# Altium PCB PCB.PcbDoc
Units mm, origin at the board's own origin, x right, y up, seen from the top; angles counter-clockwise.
Board outline 41 x 25.36 mm, 2 copper layers (TOP, BOTTOM), stack 1.586 mm thick; 68 components, 25 nets, 184 pads, 70 vias.
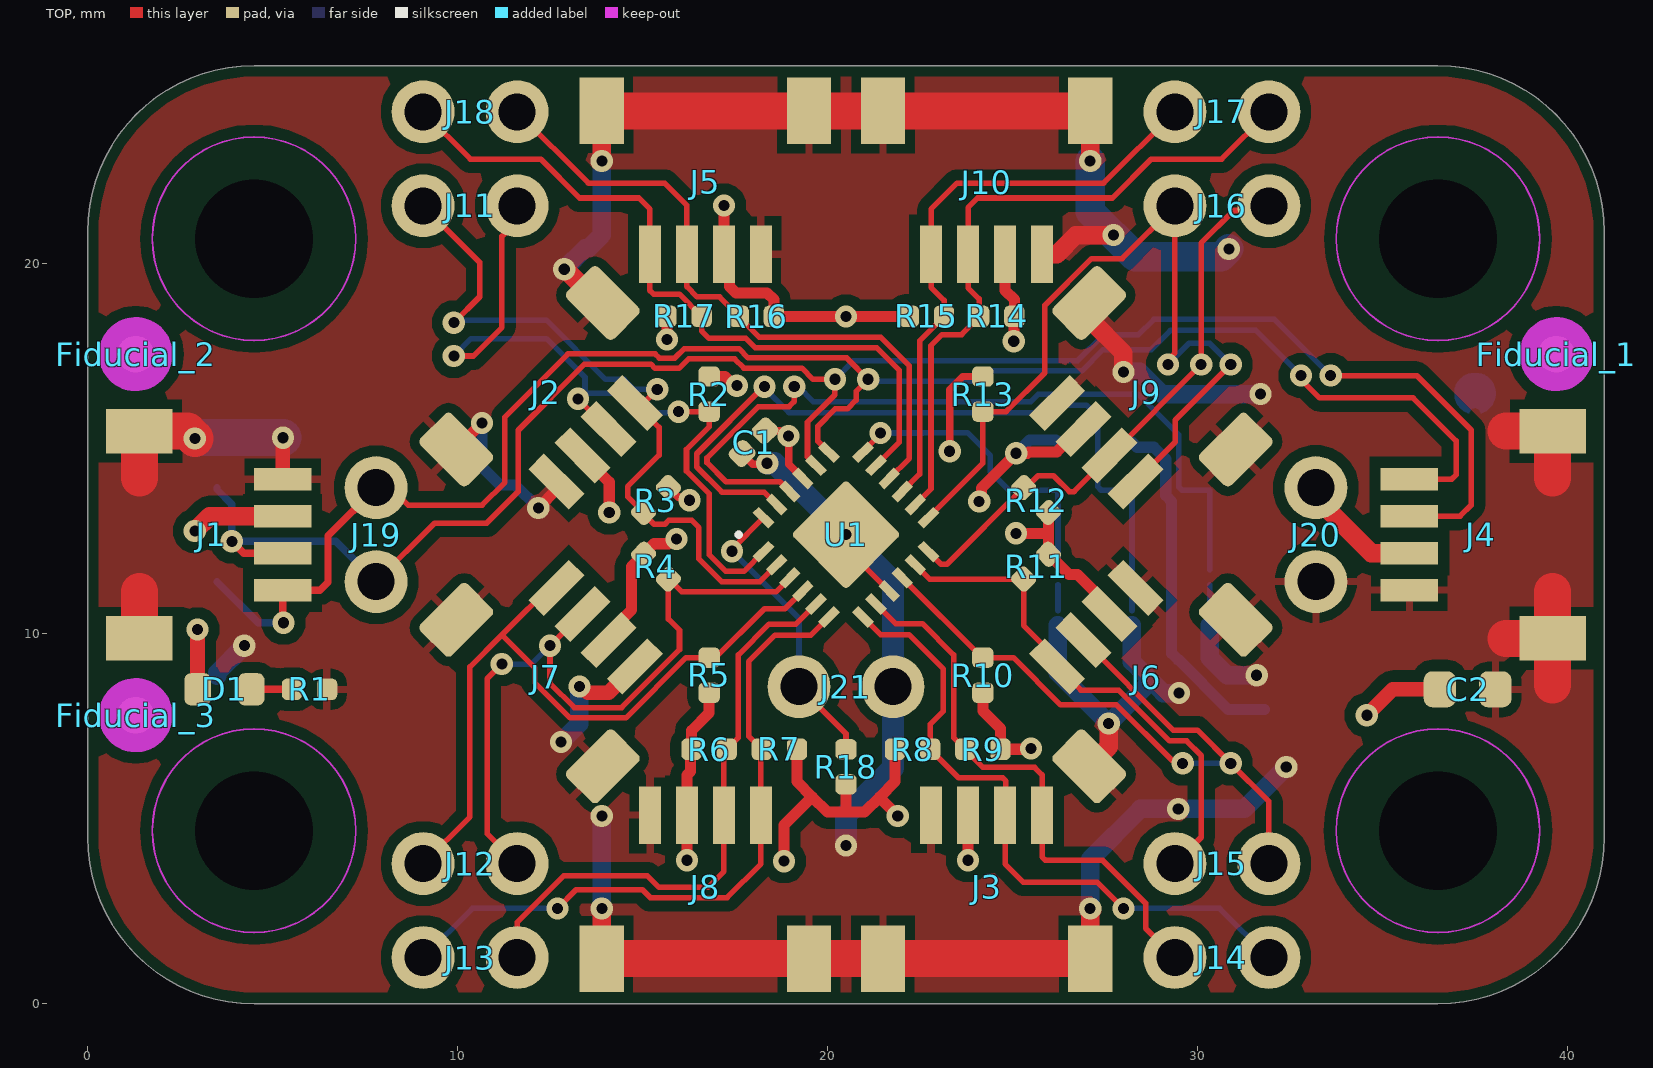
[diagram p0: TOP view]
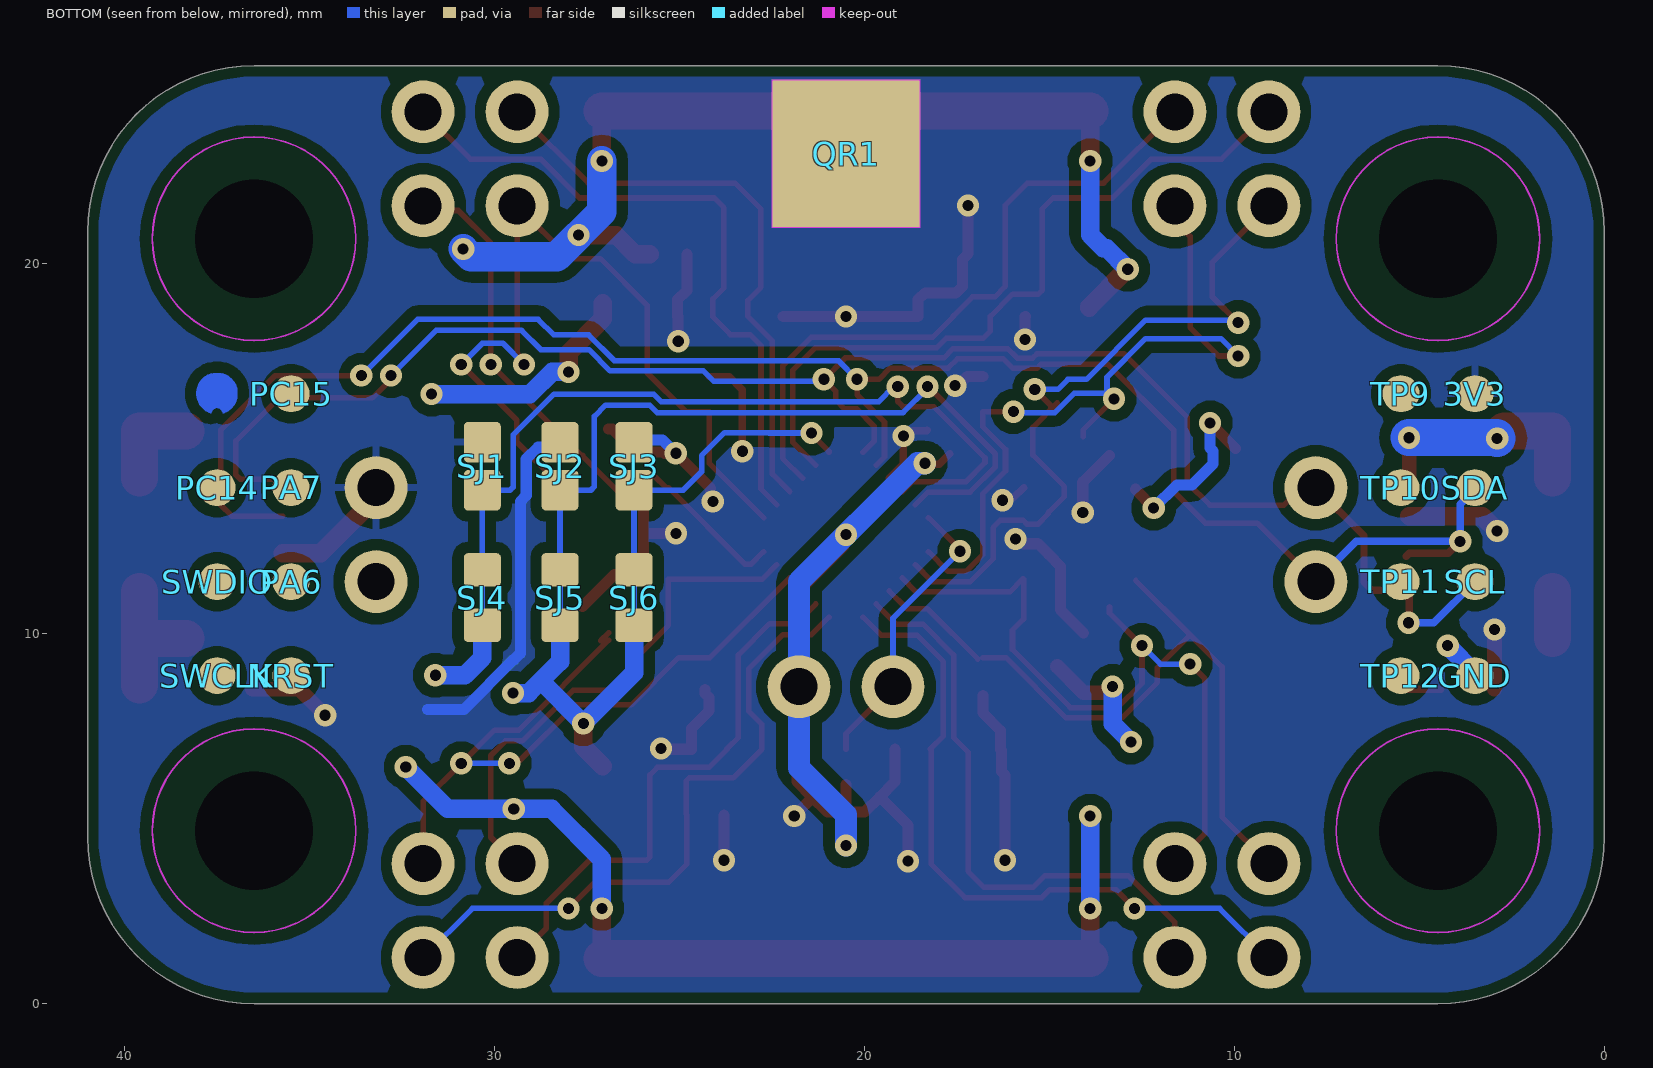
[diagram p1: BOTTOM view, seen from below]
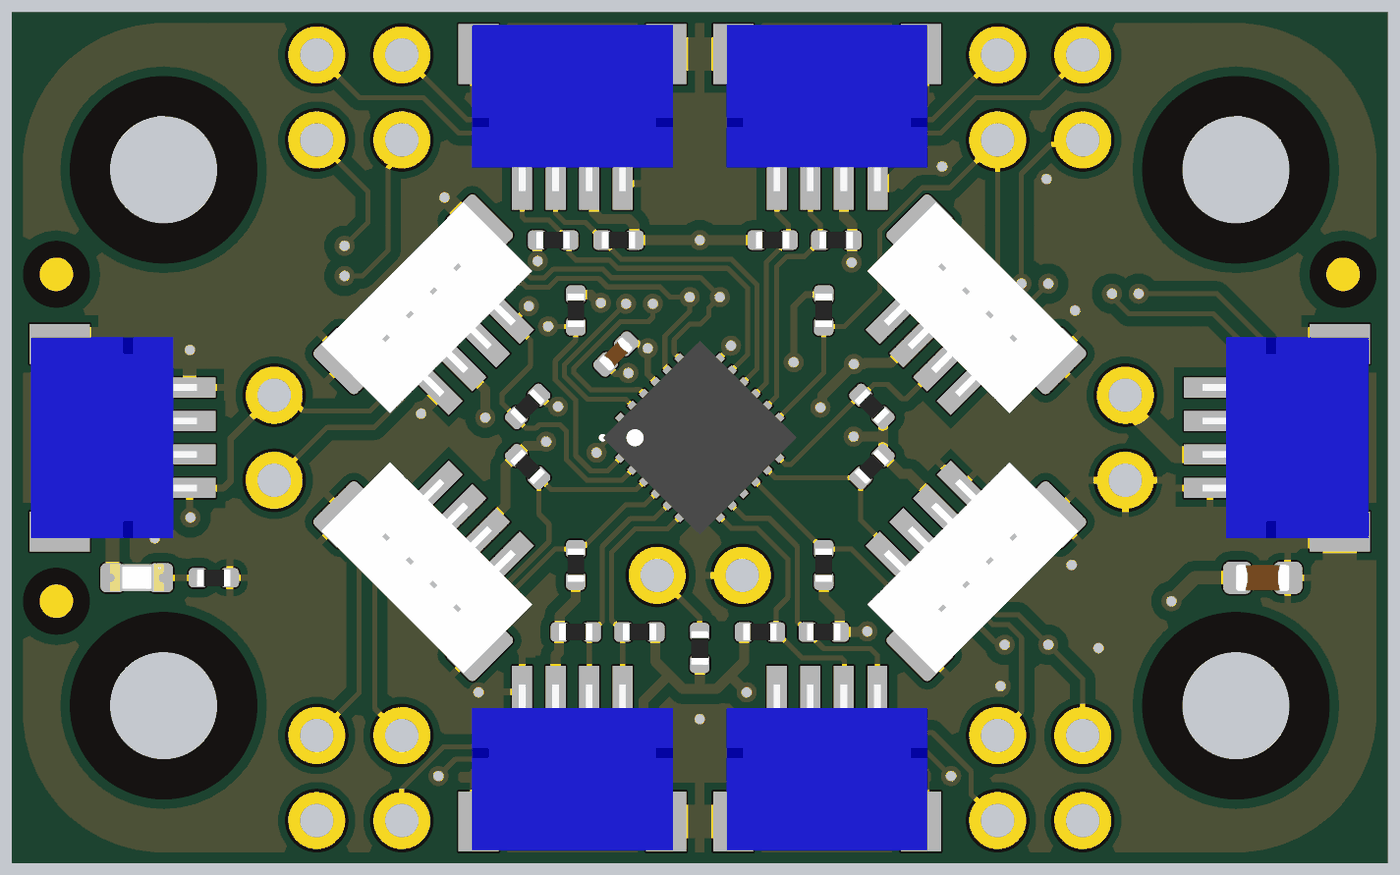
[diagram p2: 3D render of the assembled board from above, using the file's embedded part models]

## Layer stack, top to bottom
Top Solder: solder mask 0.01, Solder Resist, Dk 3.5
TOP: signal copper 0.018
Dielectric: core 1.55, FR-4, Dk 4.8
BOTTOM: signal copper 0.018
Bottom Solder: solder mask 0.01, Solder Resist, Dk 3.5

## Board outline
0,4.5 0,20.86 cw(c4.5,20.86) 4.5,25.36 36.5,25.36 cw(c36.5,20.86) 41,20.86 41,4.5 cw(c36.5,4.5) 36.5,0 4.5,0 cw(c4.5,4.5)

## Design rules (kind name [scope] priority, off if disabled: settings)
BoardOutlineClearance Mousebites [(ObjectKind = 'Pad') And (Name = 'Free-MOUSEBITE')] p1: gap=0 ignorepadtopadclearanceinfootprint=FALSE
BoardOutlineClearance Silks [(OnLayer('Top Overlay') OR OnLayer('Bottom Overlay'))] p2: gap=0 ignorepadtopadclearanceinfootprint=FALSE
BoardOutlineClearance [All] p3: gap=0.3 ignorepadtopadclearanceinfootprint=FALSE
Clearance COPPER_0.3mm [All] p1: gap=0.127 ignorepadtopadclearanceinfootprint=FALSE except(0.3: Arc-Fill Arc-Poly Arc-Region Track-Fill Track-Poly Track-Region SMDPad-Fill SMDPad-Poly SMDPad-Region THPad-Fill THPad-Poly THPad-Region Via-Fill Via-Poly Via-Region Fill-Fill Fill-Poly Fill-Region Poly-Poly Poly-Region Region-Region)
Clearance "Generic clearance 0.15mm" [All] p2: gap=0.15 ignorepadtopadclearanceinfootprint=FALSE
ComponentClearance [All] p1: gap=0.2 collisioncheckmode=3 verticalgap=0 showdistances=TRUE
DiffPairsRouting USB [InDifferentialPairClass('USB')] p1: maxlimit=0.15 minlimit=0.15 mostfreqgap=0.15 toplayer_minwidth=0.15 toplayer_maxwidth=0.21 toplayer_prefwidth=0.2 bottomlayer_minwidth=0.15 bottomlayer_maxwidth=0.21 bottomlayer_prefwidth=0.2 impedanceprofiledriven=TRUE impedanceprofileid={E6B00C31-4C8E-439C-824F-D2B2CDC26F9C} impedanceprofilevalue=90.000000 maxuncoupledlength=12.7
Height [All] p1: minheight=0 maxheight=30 prefheight=12.7
HoleSize [All] p1: absolutevalues=TRUE maxlimit=30 minlimit=0.3 maxpercent=80.000 minpercent=20.000
HoleToHoleClearance [All] p1: gap=0.25 allowstackedmicrovias=FALSE
MinimumAnnularRing [All] p1: minimumring=0.15
MinimumSolderMaskSliver [All] p1: minsoldermaskwidth=0.2
NetAntennae NetAntennaeGND [InNet('GND')] p1: netantennaetolerance=10
NetAntennae NetAntennae_1 [InNet('NetSJ1_2')] p2: netantennaetolerance=10
NetAntennae NetAntennae_3 [InNet('NetSJ3_2')] p3: netantennaetolerance=10
NetAntennae NetAntennae_2 [InNet('NetSJ2_2')] p4: netantennaetolerance=10
NetAntennae [All] p5: netantennaetolerance=0
PlaneConnect [All] p1: pad.planeconnectstyle=Relief pad.reliefexpansion=0.508 pad.reliefentries=4 pad.reliefconductorwidth=0.254 pad.reliefairgap=0.254 via.planeconnectstyle=Direct via.reliefexpansion=0.508 via.reliefentries=4 via.reliefconductorwidth=0.254 via.reliefairgap=0.254
PolygonConnect PolygonConnect_1 [(ObjectKind = 'Pad') And (Name = 'QR1-PAD')] p1: connectstyle=Direct reliefconductorwidth=0.254 reliefentries=4 polygonreliefangle="90 Angle" airgapwidth=0.254
PolygonConnect [All] p2: thpad.connectstyle=Relief thpad.reliefconductorwidth=0.2 thpad.reliefentries=4 thpad.polygonreliefangle="90 Angle" thpad.airgapwidth=0.254 smdpad.connectstyle=Relief smdpad.reliefconductorwidth=0.2 smdpad.reliefentries=4 smdpad.polygonreliefangle="90 Angle" smdpad.airgapwidth=0.254 via.connectstyle=Direct via.reliefconductorwidth=0.254 via.reliefentries=4 via.polygonreliefangle="90 Angle" via.airgapwidth=0.254
RoomDefinition TOP [InComponentClass('TOP')] p1: confinementstyle=ConfineIn formatcopy=TRUE lockcomponents=FALSE outline 43.1,2.28 49.1,2.28 49.1,15.88 43.1,15.88
RoutingVias StandardVias [All] p1: holewidth=0.3 width=0.6 viastyle="Through Hole" minholewidth=0.3 minwidth=0.6 maxholewidth=0.3 maxwidth=0.6
SMDToCorner [All] p1: distance=39370
ShortCircuit ShortCircuit_1 [InNet('NetSJ1_2') vs InNet('GND')] p1: allowed=TRUE
ShortCircuit ShortCircuit_3 [InNet('NetSJ3_2') vs InNet('GND')] p2: allowed=TRUE
ShortCircuit ShortCircuit_2 [InNet('NetSJ2_2') vs InNet('GND')] p3: allowed=TRUE
ShortCircuit [All] p4: allowed=FALSE
SilkToSilkClearance [All] p1: silktosilkclearance=0.2
SilkToSolderMaskClearance [IsPad] p1: minsilkscreentomaskgap=0.15 clearancetoexposedcopper=TRUE
SolderMaskExpansion VIAtented [IsVia] p1: expansion=0.102 istentingtop=TRUE
SolderMaskExpansion [All] p2: expansion=0.05 istentingtop=FALSE
SupplyNets "Schematic Supply Nets_1" [InNet('GND')] p1: voltage=0.000
SupplyNets "Schematic Supply Nets" [InNet('+3V3')] p2: voltage=0.000
UnConnectedPin [All] p1:
UnRoutedNet [not WithinRoom('K36')] p1: checkbadconnections=TRUE
ViasUnderSMD [All] p1: allowed=FALSE
Width StandardTraces [All] p1: maxlimit=5 minlimit=0.15 preferedwidth=0.15 minimp=50.000000 maximp=50.000000 favimp=50.000000
18 further rules are at their usual default settings.

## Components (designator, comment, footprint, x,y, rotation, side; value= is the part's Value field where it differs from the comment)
3V3 "Test point 1.00mm" TP-1.00MM 3.5,16.49 r90 bottom locked
C1 "0402B104K160CT" CAP-0402 18,15.18 r225 top value=100nF
C2 "GRM188R61C475KAAJD" CAP-0603 37.3,8.5 r180 top value=4.7µF
D1 "HSMG-C190" LEDC1608X80N-AK 3.7,8.5 r180 top locked
Fiducial_1 "Fiducial mark 1mm" "Fiducial mark 1mm-Footprint-1" 39.7,17.56 r270 top
Fiducial_2 "Fiducial mark 1mm" "Fiducial mark 1mm-Footprint-1" 1.3,17.56 r270 top locked
Fiducial_3 "Fiducial mark 1mm" "Fiducial mark 1mm-Footprint-1" 1.3,7.8 r270 top locked
GND "Test point 1.00mm" TP-1.00MM 3.5,8.87 r90 bottom locked
J1 "SM04B-SRSS-TB(LF)(SN)" SM04B-SRSS-TB(LF)(SN)-Footprint-1 3.337,12.68 r90 top locked
J2 "BM04B-SRSS-TBT(LF)(SN)(P)" BM04B-SRSS-TB 12.6,16.31 r45 top locked
J3 "SM04B-SRSS-TB(LF)(SN)" SM04B-SRSS-TB(LF)(SN)-Footprint-1 24.3,3.16 r180 top locked
J4 "SM04B-SRSS-TB(LF)(SN)" SM04B-SRSS-TB(LF)(SN)-Footprint-1 37.663,12.68 r270 top locked
J5 "SM04B-SRSS-TB(LF)(SN)" SM04B-SRSS-TB(LF)(SN)-Footprint-1 16.7,22.2 r0 top locked
J6 "BM04B-SRSS-TBT(LF)(SN)(P)" BM04B-SRSS-TB 28.4,9.05 r225 top locked
J7 "BM04B-SRSS-TBT(LF)(SN)(P)" BM04B-SRSS-TB 12.6,9.05 r135 top locked
J8 "SM04B-SRSS-TB(LF)(SN)" SM04B-SRSS-TB(LF)(SN)-Footprint-1 16.7,3.16 r180 top locked
J9 "BM04B-SRSS-TBT(LF)(SN)(P)" BM04B-SRSS-TB 28.4,16.31 r315 top locked
J10 "SM04B-SRSS-TB(LF)(SN)" SM04B-SRSS-TB(LF)(SN)-Footprint-1 24.3,22.2 r0 top locked
J11 "HEADER TH 2.54mm VERT. 1x002POS" "PIN HEADER 2.54mm VERT. 1x2POS" 10.34,21.57 r180 top locked
J12 "HEADER TH 2.54mm VERT. 1x002POS" "PIN HEADER 2.54mm VERT. 1x2POS" 10.34,3.79 r180 top locked
J13 "HEADER TH 2.54mm VERT. 1x002POS" "PIN HEADER 2.54mm VERT. 1x2POS" 10.34,1.25 r180 top locked
J14 "HEADER TH 2.54mm VERT. 1x002POS" "PIN HEADER 2.54mm VERT. 1x2POS" 30.66,1.25 r180 top locked
J15 "HEADER TH 2.54mm VERT. 1x002POS" "PIN HEADER 2.54mm VERT. 1x2POS" 30.66,3.79 r180 top locked
J16 "HEADER TH 2.54mm VERT. 1x002POS" "PIN HEADER 2.54mm VERT. 1x2POS" 30.66,21.57 r180 top locked
J17 "HEADER TH 2.54mm VERT. 1x002POS" "PIN HEADER 2.54mm VERT. 1x2POS" 30.66,24.11 r180 top locked
J18 "HEADER TH 2.54mm VERT. 1x002POS" "PIN HEADER 2.54mm VERT. 1x2POS" 10.34,24.11 r180 top locked
J19 "HEADER TH 2.54mm VERT. 1x002POS" "PIN HEADER 2.54mm VERT. 1x2POS" 7.8,12.68 r90 top locked
J20 "HEADER TH 2.54mm VERT. 1x002POS" "PIN HEADER 2.54mm VERT. 1x2POS" 33.2,12.68 r270 top locked
J21 "HEADER TH 2.54mm VERT. 1x002POS" "PIN HEADER 2.54mm VERT. 1x2POS" 20.5,8.57 r0 top locked
NRST "Test point 1.00mm" TP-1.00MM 35.5,8.87 r180 bottom locked
PA6 "Test point 1.00mm" TP-1.00MM 35.5,11.41 r180 bottom locked
PA7 "Test point 1.00mm" TP-1.00MM 35.5,13.95 r180 bottom locked
PC14 "Test point 1.00mm" TP-1.00MM 37.5,13.95 r180 bottom locked
PC15 "Test point 1.00mm" TP-1.00MM 35.5,16.49 r180 bottom locked
QR1 "QR CODE 4x4mm" "QR CODE 4x4mm" 20.5,22.98 r180 bottom
R1 "CRCW04021K00FKEDC" RES-0402 6,8.5 r180 top value=1k
R2 "RC0402FR-074K7L" RES-0402 16.8,16.48 r90 top value=4.7k
R3 "RC0402FR-074K7L" RES-0402 15.364,13.616 r45 top locked value=4.7k
R4 "RC0402FR-074K7L" RES-0402 15.364,11.816 r135 top locked value=4.7k
R5 "RC0402FR-074K7L" RES-0402 16.8,8.88 r270 top value=4.7k
R6 "RC0402FR-074K7L" RES-0402 16.8,6.88 r180 top locked value=4.7k
R7 "RC0402FR-074K7L" RES-0402 18.7,6.88 r0 top locked value=4.7k
R8 "RC0402FR-074K7L" RES-0402 22.3,6.88 r180 top locked value=4.7k
R9 "RC0402FR-074K7L" RES-0402 24.2,6.88 r0 top locked value=4.7k
R10 "RC0402FR-074K7L" RES-0402 24.2,8.88 r270 top value=4.7k
R11 "RC0402FR-074K7L" RES-0402 25.636,11.816 r45 top locked value=4.7k
R12 "RC0402FR-074K7L" RES-0402 25.636,13.616 r315 top locked value=4.7k
R13 "RC0402FR-074K7L" RES-0402 24.2,16.48 r90 top value=4.7k
R14 "RC0402FR-074K7L" RES-0402 24.575,18.58 r0 top locked value=4.7k
R15 "RC0402FR-074K7L" RES-0402 22.675,18.58 r180 top locked value=4.7k
R16 "RC0402FR-074K7L" RES-0402 18.075,18.58 r0 top locked value=4.7k
R17 "RC0402FR-074K7L" RES-0402 16.125,18.58 r180 top locked value=4.7k
R18 "RC0402FR-074K7L" RES-0402 20.5,6.405 r90 top locked value=4.7k
SCL "Test point 1.00mm" TP-1.00MM 3.5,11.41 r90 bottom locked
SDA "Test point 1.00mm" TP-1.00MM 3.5,13.95 r90 bottom locked
SJ1 "SOLDER JUMPER OPEN 0603" SJ 30.33,14.53 r90 bottom locked
SJ2 "SOLDER JUMPER OPEN 0603" SJ 28.23,14.53 r90 bottom locked
SJ3 "SOLDER JUMPER OPEN 0603" SJ 26.23,14.53 r90 bottom locked
SJ4 "SOLDER JUMPER CLOSED 0603" "SJ 0603 CLOSED" 30.33,10.98 r90 bottom locked
SJ5 "SOLDER JUMPER CLOSED 0603" "SJ 0603 CLOSED" 28.23,10.98 r90 bottom locked
SJ6 "SOLDER JUMPER CLOSED 0603" "SJ 0603 CLOSED" 26.23,10.98 r90 bottom locked
SWCLK "Test point 1.00mm" TP-1.00MM 37.5,8.87 r180 bottom locked
SWDIO "Test point 1.00mm" TP-1.00MM 37.5,11.41 r180 bottom locked
TP9 "Test point 1.00mm" TP-1.00MM 5.5,16.49 r0 bottom locked
TP10 "Test point 1.00mm" TP-1.00MM 5.5,13.95 r0 bottom locked
TP11 "Test point 1.00mm" TP-1.00MM 5.5,11.41 r0 bottom locked
TP12 "Test point 1.00mm" TP-1.00MM 5.5,8.87 r0 bottom locked
U1 "TCA9548ARGER" PQFN50P400X400X100_HS-25N 20.5,12.68 r45 top locked

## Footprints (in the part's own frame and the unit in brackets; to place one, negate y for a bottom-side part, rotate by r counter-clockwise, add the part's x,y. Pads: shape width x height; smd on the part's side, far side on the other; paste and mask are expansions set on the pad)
BM04B-SRSS-TB [mm]
  rect 0.6x1.55 smd mask+0.05: 1(-1.5,-1.6) 2(-0.5,-1.6) 3(0.5,-1.6) 4(1.5,-1.6)
  rrect25% 1.2x1.8 smd mask+0.05: FIX(-2.8,0.922) FIX(2.8,0.922)
  body extent -3,-1.8 3,1.8, height 4.33
CAP-0402 [mm] "Chip Capacitor, 2-Leads, Body  0402 (in) 1005 (mm), IPC Medium Density"
  rrect52% 0.63x0.58 smd mask+0.05: 1(-0.435,0) 2(0.435,0)
  body extent -0.5,-0.25 0.5,0.25, height 0.5
CAP-0603 [mm] "Chip Capacitor, Body 0603 imperial,1.6x0.8mm, IPC High Density"
  rrect51% 0.87x0.97 smd mask+0.05: 1(-0.75,0) 2(0.75,0)
  body extent -0.8,-0.4 0.8,0.4, height 0.8
"Fiducial mark 1mm-Footprint-1" [mm]
  round 1 smd paste-10 mask+0.5: 1(0,0)
  TOP keep-out circle w1: c0,0 r0.5
LEDC1608X80N-AK [mm]
  rrect50% 0.72x0.87 smd: A(0.725,0) C(-0.725,0)
  body extent -0.8,-0.4 0.8,0.4, height 0.79
"PIN HEADER 2.54mm VERT. 1x2POS" [mm]
  round 1.7 hole 1 mask+0.1: 1(-1.27,0) 2(1.27,0)
PQFN50P400X400X100_HS-25N [mm] "PQFN, 24-Leads, Body 4,00x4,00mm, Pitch 0,50mm, Thermal Pad 2,10x2,10mm, IPC Medium Density"
  rect 0.6x0.24 smd mask+0.05: 1(-1.9,1.25) 2(-1.9,0.75) 3(-1.9,0.25) 4(-1.9,-0.25) 5(-1.9,-0.75) 6(-1.9,-1.25) 13(1.9,-1.25) 14(1.9,-0.75) 15(1.9,-0.25) 16(1.9,0.25) 17(1.9,0.75) 18(1.9,1.25)
  rect 0.24x0.6 smd mask+0.05: 7(-1.25,-1.9) 8(-0.75,-1.9) 9(-0.25,-1.9) 10(0.25,-1.9) 11(0.75,-1.9) 12(1.25,-1.9) 19(1.25,1.9) 20(0.75,1.9) 21(0.25,1.9) 22(-0.25,1.9) 23(-0.75,1.9) 24(-1.25,1.9)
  rrect10% 2.1x2.1 smd paste-5 mask+0.05: 25(0,0)
  silkscreen extent -2.1,2 -2,2.1, body extent -2.05,-2.05 2.05,2.05, height 1
"QR CODE 4x4mm" [mm]
  rect 4x4 smd paste-2539.97 mask+0.1: PAD(0,0)
  TOP keep-out region: -2,2 2,2 2,-2 -2,-2
RES-0402 [mm] "Chip Resistor, 2-Leads, Body  0402 (in) 1005 (mm), IPC Medium Density"
  rrect51% 0.55x0.58 smd mask+0.05: 1(-0.475,0) 2(0.475,0)
  body extent -0.5,-0.25 0.5,0.25, height 0.34
SJ [mm]
  rrect25% 1.1x1 smd paste-2539.97 mask+0.1: 1(0.65,0) 2(-0.65,0)
"SJ 0603 CLOSED" [mm]
  rrect25% 0.9x1 smd paste-2539.97 mask+0.1: 1(0.75,0) 2(-0.75,0)
  TOP lines w0.15: -0.35,0 0.35,0
SM04B-SRSS-TB(LF)(SN)-Footprint-1 [mm]
  rect 0.6x1.55 smd mask+0.05: 1(1.5,-1.937) 2(0.5,-1.937) 3(-0.5,-1.937) 4(-1.5,-1.937)
  rect 1.2x1.8 smd mask+0.05: FIX(-2.8,1.938) FIX(2.8,1.938)
  body extent -3,-2.16 3,2.8, height 2.98
TP-1.00MM [mm]
  rrect100% 1x1 smd paste-2.54: X(0,0)

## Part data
3V3 GND NRST PA6 PA7 PC14 PC15 SCL SDA SWCLK SWDIO TP9 TP10 TP11 TP12: library part UT0013-A.6, Manufacturer="This is not a component"
C1: library part C0012-A.15, "CAP CHIP 0402 100nF 10% 16V X7R", Case Code (Imperial)=0402, Dielectric=X7R, Manufacturer=Walsin, Tolerance=10%, Voltage=16V
C2: library part C0054-A.16, "CAP CHIP 0603 4.7uF 10% 16V X5R", Case Code (Imperial)=0603, Dielectric=X5R, Manufacturer=Murata, Manufacturer 3="Samsung Electro-Mechanics", Part number 2=GRM188R61C475KE11D, Part number 3=CL10A475KO8NNNC, Tolerance=10%, Voltage=16V
D1: library part L0009-A.5, "LED SMD 0603 GREEN/568 15mcd 120^", Manufacturer=Broadcom
Fiducial_1 Fiducial_2 Fiducial_3: library part UT0023-A.7, "Fiducial mark 1mm clearance 2mm"
J1 J3 J4 J5 J8 J10: library part J0005-A.2, "CONN JST 4POS SIDE 1MM TIN QWIIC", Manufacturer=JST
J2 J6 J7 J9: library part J0478-A.3, "CONN JST 4POS VERTICAL 1mm pitch, color neutral, suction tape, tin, QWIIC", Manufacturer=JST
J11 J12 J13 J14 J15 J16 J17 J18 J19 J20 J21: library part J0238-A.5
QR1: library part QR-0001-A.5, "QR CODE 4x4mm on layer 34 (This is not a component)", Manufacturer="This is not a component"
R1: library part R0007-A.24, "RES CHIP 0402 1k 1% 1/16W", Case Code (Imperial)=0402, Manufacturer=Vishay, Power=62.5mW, Temperature Coefficient=100ppm, Tolerance=1%
R2 R3 R4 R5 R6 R7 R8 R9 R10 R11 R12 R13 R14 R15 R16 R17 R18: library part R0013-A.24, "RES CHIP 0402 4k7 1% 1/16W", Case Code (Imperial)=0402, Manufacturer=YAGEO, Power=62.5mW, Temperature Coefficient=200ppm, Tolerance=1%
SJ1 SJ2 SJ3: library part UT0038-A.5
SJ4 SJ5 SJ6: library part UT0039-A.4
U1: library part U0170-A.3, "IC I2C SWITCH 8CH with RST, 5V tolerant pins, 1V8 to 5V buses, VQFN24 4x4mm pitch 0.5mm", Manufacturer="Texas Instruments"

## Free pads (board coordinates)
  round 3 hole 3.2 unplated paste-2539.97 mask+1.3: MH(4.5,4.68) MH(4.5,20.68) MH(36.5,4.68) MH(36.5,20.68)

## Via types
v1: diameter 0.6, hole 0.3, TOP to BOTTOM, tented both sides, 70 vias

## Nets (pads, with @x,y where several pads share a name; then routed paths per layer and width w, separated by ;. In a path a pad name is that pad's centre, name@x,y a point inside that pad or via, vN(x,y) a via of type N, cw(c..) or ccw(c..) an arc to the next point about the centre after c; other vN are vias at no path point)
+3V3: 3V3.X C1.1 C2.2 D1.A J1.2 J2.2 J3.2 J4.2 J5.2 J6.2 J7.2 J8.2 J9.2 J10.2 J20.1 QR1.PAD R2.2 R3.2 R4.2 R5.2 R6.2 R7.2 R8.2 R9.2 R10.2 R11.2 R12.2 R13.2 R14.2 R15.2 R16.2 R17.2 R18.1 SJ1.1 SJ2.1 SJ3.1 U1.21 | length 68.4
  TOP w0.2: R3.2 15.965,13.687 16.192,13.687 v1(16.269,13.61) ; C1.1@18.3,15.5 18.314,15.486 18.704,15.486 18.839,15.351 v1(18.948,15.351) ; v1@18.935,15.265 18.948,15.252 18.948,14.586 U1.21 ; v1(23.303,14.936) 23.303,16.599 23.659,16.955 R13.2
  TOP w0.3: J2.2 14.1,14.103 v1(14.1,13.28) ; J7.2@14.085,10.028 14.7,10.643 14.7,11.824 R4.2 15.312,12.436 15.707,12.436 15.835,12.563 v1(15.916,12.563) ; R17.2 15.657,18.573 15.657,17.96 v1(15.663,17.953) ; v1(16.2,3.88) J8.2 16.2,6.18 16.3,6.28 16.3,6.855 R6.2 16.325,7.38 16.8,7.855 R5.2@16.8,8.33 ; R2.2 17.231,16.955 17.478,16.708 v1(17.549,16.708) ; v1(17.2,21.58) J5.2 17.349,20.114 17.349,19.387 17.526,19.211 18.369,19.211 18.55,19.03 R16.2 v1(20.5,18.58) R15.2 ; v1(18.825,3.855) 18.825,4.83 19.587,5.593 ; R7.2 19.175,6.005 19.587,5.593 ; R18.1 20.5,5.18 ; R8.2 21.825,6.005 21.413,5.593 ; v1(21.9,5.08) 21.413,5.567 21.413,5.593 ; v1(23.8,3.88) J3.2 ; v1(24.1,13.58) 24.157,13.637 24.157,13.937 v1(25.1,14.88) 25.4,14.88 25.436,14.916 26.196,14.916 26.812,15.532 J9.2 ; R10.2@24.307,8.497 24.307,8.387 24.2,8.28 24.2,7.911 24.675,7.436 R9.2 25.48,6.88 v1(25.5,6.9) ; J10.2 24.8,19.28 25.05,19.03 R14.2 25.042,18.572 25.042,17.918 v1(25.033,17.909) ; v1(25.094,12.716) 25.972,12.716 ; R12.2 25.972,12.716 ; J6.2@27.622,10.735 26.757,11.6 26.524,11.6 R11.2 25.972,12.716 ; 19.587,5.593 20,5.18 20.5,5.18 ; 20.5,5.18 21,5.18 21.413,5.593
  TOP w0.4: D1.A v1(2.975,10.118) ; v1(34.578,7.799) 35.279,8.5 C2.2
  TOP w0.5: v1(2.9,12.78) 3.3,13.18 J1.2 ; J20.1 33.2,13.68 34.7,12.18 J4.2
  BOTTOM w0.3: v1@18.799,3.88 v1(18.825,3.855) ; v1(25.1,14.88) 25.456,15.236 26.174,15.236 SJ3.1 ; SJ2.1 28.367,15.043 28.83,15.043 29.144,14.729 29.144,13.736 29.3,13.58 29.3,9.476 29.476,9.3 29.49,9.3 30.832,7.958 31.815,7.958
GND: C1.2 C2.1 GND.X J1.1 J1.FIX J2.1 J2.FIX J3.1 J3.FIX J4.1 J4.FIX J5.1 J5.FIX J6.1 J6.FIX J7.1 J7.FIX J8.1 J8.FIX J9.1 J9.FIX J10.1 J10.FIX J20.2 J21.2 R1.1 SJ4.2 SJ5.2 SJ6.2 U1.9 U1.25 | length 110.8
  TOP w0.15: v1(20.5,12.68) 20.5,12.326 U1.9
  TOP w0.2: C1.2 17.977,14.588 18.347,14.588 v1(18.37,14.611)
  TOP w0.3: J2.FIX@9.968,15.011 v1(10.659,15.702) ; v1(12.183,13.4) 12.68,13.897 12.68,13.909 J2.1@12.671,13.918
  TOP w0.4: J1.1 5.275,15.291 v1(5.284,15.301) ; v1(13.294,8.579) 13.348,8.579 13.519,8.408 14.079,8.408 J7.1
  TOP w0.5: v1(12.884,19.854) 12.911,19.854 13.928,18.837 J2.FIX@13.928,18.81 ; J8.FIX@13.9,1.222 v1(13.9,2.58) ; v1(13.9,22.78) J5.FIX@13.9,24.137 ; J10.1 26.2,20.262 26.715,20.778 v1(27.733,20.778) ; J6.FIX@27.072,6.423 27.072,6.418 27.6,6.946 v1(27.6,7.58) ; J9.FIX@27.072,18.942 27.072,18.518 28,17.59 v1(28,17.08) ; J3.FIX@27.1,1.222 v1(27.1,2.58) ; v1(27.1,22.78) J10.FIX@27.1,24.138
  TOP w1: J1.FIX@1.399,9.88 1.399,11.143 ; 1.399,14.218 1.399,15.48 2.7,15.48 v1(2.9,15.28) ; J8.FIX@13.9,1.222 19.5,1.222 J3.FIX@27.1,1.222 ; J5.FIX@13.9,24.137 J10.FIX@27.1,24.137 ; 38.338,9.88 J4.FIX@39.601,9.88 ; 38.338,15.48 39.601,15.48 39.601,14.218 ; 39.601,8.618 J4.FIX@39.601,9.88 ; 39.601,11.142 J4.FIX@39.601,9.88
  BOTTOM w0.3: v1(10.659,15.702) 10.659,15.02 10.585,14.947 10.585,14.595 11.154,14.026 11.557,14.026 v1(12.183,13.4)
  BOTTOM w0.5: GND.X 3.5,8.943 v1(4.237,9.68) ; v1(12.8,7.08) 13.294,7.574 v1(13.294,8.579) ; v1(12.884,19.854) 13.456,20.426 13.546,20.426 13.9,20.78 v1(13.9,22.78) ; v1(13.9,2.58) v1(13.9,5.08) ; SJ6.2 26.23,8.95 v1(27.6,7.58) 28.715,8.695 28.715,8.765 ; v1(27.1,2.58) 27.1,3.907 28.459,5.266 v1(29.479,5.266) 31.266,5.266 v1(32.4,6.4) ; v1(28,17.08) 28.443,17.08 29.043,16.48 v1@31.673,16.48 ; SJ5.2 28.23,9.25 28.715,8.765 ; v1(29.5,8.4) 29.08,8.4 28.715,8.765 ; SJ4.2 30.33,9.35 30.8,8.88 v1(31.6,8.88)
  BOTTOM w0.6: v1(18.37,14.611) 18.569,14.611 21.77,11.41 J21.2 21.77,6.381 20.5,5.111 v1(20.5,4.28)
  BOTTOM w0.8: v1(27.1,22.78) 27.1,21.411 28.318,20.193 30.635,20.193 v1(30.847,20.406)
  BOTTOM w1: v1(2.9,15.28) 2.921,15.301 v1(5.284,15.301)
  other v1: 31.7,16.48
NetD1_C: D1.C R1.2 | length 1.1
  TOP w0.2: D1.C R1.2
NetSJ1_2: SJ1.2 SJ4.1 U1.22 | length 21.6
  TOP w0.15: U1.22 18.71,14.117 18.585,14.117 18.578,14.109 17.264,14.109 16.743,14.629 16.743,14.754 18.132,16.143 18.963,16.143 19.1,16.28 v1(19.1,16.68)
  BOTTOM w0.15: v1(19.1,16.68) 19.211,16.68 19.613,16.278 25.498,16.278 25.7,16.48 28.392,16.48 29.496,15.377 29.496,13.968 29.584,13.88 SJ1.2 SJ4.1
NetSJ2_2: SJ2.2 SJ5.1 U1.23 | length 20.1
  TOP w0.15: v1(18.3,16.68) 18.278,16.68 16.466,14.868 16.466,14.515 17.149,13.832 18.287,13.832 U1.23
  BOTTOM w0.15: v1(18.3,16.68) 18.3,16.638 18.96,15.978 25.604,15.978 25.806,16.18 27,16.18 27.3,15.88 27.3,13.98 27.4,13.88 SJ2.2 SJ5.1
NetSJ3_2: SJ3.2 SJ6.1 U1.18 | length 8.6
  TOP w0.15: U1.18 20.96,14.931 21.432,15.404 v1(21.432,15.428)
  BOTTOM w0.15: v1(21.432,15.428) 22.571,15.428 22.58,15.438 23.782,15.438 24.4,14.82 24.4,14.38 24.9,13.88 SJ3.2 SJ6.1
R\E\S\E\T\_1: J21.1 R18.2 U1.24 | length 7.9
  TOP w0.15: v1(17.419,12.233) 17.419,12.286 U1.24 ; J21.1 20.5,7.3 R18.2
  BOTTOM w0.15: v1(17.419,12.233) 19.23,10.422 J21.1
SC0_1: J2.4 J11.2 R3.1 U1.2 | length 20
  TOP w0.15: J11.2 10.6,20.04 10.6,19.11 v1(9.9,18.41) ; J2.4 15.451,15.58 15.451,14.831 14.6,13.98 14.6,13.708 R3.1 15.028,13.248 15.314,12.962 15.604,12.962 15.708,13.065 16.332,13.065 16.523,12.874 16.523,12.027 17.137,11.413 18.172,11.413 U1.2 ; J2.4@14.969,16.049 14.969,16.178 v1(15.399,16.608)
  BOTTOM w0.15: v1(9.9,18.41) 9.97,18.48 12.4,18.48 14,16.88 14.503,16.88 14.775,16.608 v1(15.399,16.608)
SC1_1: J7.4 J12.2 R5.1 U1.4 | length 19.7
  TOP w0.15: J12.2 10.334,5.054 10.334,9.105 11.177,9.949 J7.4@12.671,11.442 ; 11.2,9.971 12.086,9.086 12.086,8.686 13.042,7.729 14.549,7.729 16.175,9.355 R5.1 ; R5.1@16.938,9.318 18.298,10.678 18.851,10.678 U1.4
SC2_1: J8.4 J13.2 R7.1 U1.6 | length 18.7
  TOP w0.15: v1(12.7,2.58) 13.202,3.082 14.995,3.082 15.209,2.868 17.288,2.868 18.2,3.78 J8.4 18.2,6.855 R7.1 17.869,7.236 17.869,9.249 18.584,9.964 19.552,9.964 U1.6
  BOTTOM w0.15: J13.2 10.4,2.58 v1(12.7,2.58)
SC3_1: J3.4 J14.2 R9.1 U1.8 | length 15.1
  TOP w0.15: U1.8 21.842,10.277 22.563,10.277 23.408,9.432 23.408,7.197 R9.1 23.725,6.862 24.199,6.388 25.596,6.388 25.8,6.184 J3.4 25.8,3.968 25.888,3.88 27.437,3.88 28.602,2.715 28.602,2.038 J14.2
SC4_1: J6.4 J15.2 R11.1 U1.11 | length 13.7
  TOP w0.15: U1.11 22.761,11.48 R11.1 25.3,10.229 J6.4@26.208,9.321 ; J6.4 26.849,8.48 27.871,8.48 29.247,7.104 29.705,7.104 30.102,6.708 30.102,4.502 J15.2
SC5_1: J9.4 J16.2 R13.1 U1.13 | length 22.8
  TOP w0.15: U1.13 24.2,14.612 R13.1 24.825,16.005 25.872,17.052 25.872,18.876 27.138,20.142 27.962,20.142 J16.2 29.39,17.592 29.2,17.402 v1(29.2,17.28) ; J9.4 29.4,15.189 29.4,15.78 v1(30.9,17.28)
  BOTTOM w0.15: v1(29.2,17.28) 29.774,17.854 30.326,17.854 v1(30.9,17.28)
SC6_1: J10.4 J17.2 R15.1 U1.15 | length 15.9
  TOP w0.15: U1.15 22.488,14.314 22.488,17.918 R15.1 23.15,19.015 22.8,19.365 22.8,21.48 23.5,22.18 27.46,22.18 J17.2
SC7_1: J5.4 J18.2 R17.1 U1.17 | length 20.1
  TOP w0.15: J18.2 10.349,22.831 12.249,22.831 13.3,21.78 14.9,21.78 15.2,21.48 J5.4 15.2,19.28 15.3,19.18 16,19.18 R17.1 16.6,18.19 16.803,17.987 17.794,17.987 18.045,17.736 21.326,17.736 21.934,17.128 21.934,15.175 U1.17
SCL_1: J1.4 J4.4 J19.2 SCL.X U1.19 | length 47.1
  TOP w0.15: J19.2 8.193,13.95 8.663,13.48 10.665,13.48 11.278,14.094 11.278,15.858 12.985,17.566 15.341,17.566 15.455,17.451 15.871,17.451 16.13,17.71 17.605,17.71 17.856,17.459 20.521,17.459 v1(21.1,16.88) 20.775,16.555 20.775,16.316 20.537,16.078 20.208,16.078 19.737,15.607 19.737,15.211 U1.19 ; v1(32.8,16.98) 32.8,16.88 33.3,16.38 35.826,16.38 36.99,15.215 36.99,14.297 36.873,14.18 J4.4
  TOP w0.2: v1(5.3,10.3) 5.275,10.325 J1.4 6.283,11.18 6.5,11.397 6.5,12.65 J19.2
  BOTTOM w0.15: v1(21.1,16.88) 21.15,16.83 24.078,16.83 24.353,17.105 26.876,17.105 27.451,17.68 28.75,17.68 29.27,18.2 31.58,18.2 v1(32.8,16.98)
  BOTTOM w0.2: SCL.X 4.61,10.3 v1(5.3,10.3)
SD0_1: J2.3 J11.1 R2.1 U1.1 | length 21.2
  TOP w0.15: v1(9.9,17.51) 10.43,17.51 11.2,18.28 11.2,20.741 11.61,21.151 J11.1 ; v1(13.253,16.352) 14.085,15.52 J2.3@14.085,15.332 ; v1(15.975,16.005) R2.1 16.8,15.594 16.189,14.983 16.189,14.4 16.8,13.789 16.8,12.142 17.252,11.69 17.742,11.69 U1.1
  BOTTOM w0.15: v1(9.9,17.51) 10.37,17.98 12.4,17.98 13.445,16.935 13.445,16.545 v1(13.253,16.352) ; v1@13.407,16.507 14.327,16.507 14.856,15.978 15.948,15.978 v1(15.975,16.005)
SD1_1: J7.3 J12.1 R4.1 U1.3 | length 19.8
  TOP w0.15: v1(11.197,9.183) 10.8,8.786 10.8,4.6 J12.1 ; v1(12.5,9.68) 12.5,8.663 13.157,8.006 14.434,8.006 16,9.572 16,10.1 15.7,10.4 R4.1 ; v1@12.6,9.68 12.6,9.78 13.378,10.558 J7.3@13.378,10.735 ; R4.1@15.711,11.491 16.065,11.136 18.603,11.136 U1.3
  BOTTOM w0.15: v1(11.197,9.183) 12.003,9.183 v1(12.5,9.68)
SD2_1: J8.3 J13.1 R6.1 U1.5 | length 16
  TOP w0.15: J13.1 11.61,2.2 12.867,3.457 15.134,3.457 15.446,3.145 16.765,3.145 17.2,3.58 J8.3 17.2,6.805 17.592,7.197 17.592,9.432 18.424,10.264 19.145,10.264 U1.5
SD3_1: J3.3 J14.1 R8.1 U1.7 | length 17.9
  TOP w0.15: U1.7 21.435,9.977 22.203,9.977 23.131,9.049 23.131,7.911 22.775,7.555 R8.1 23.545,6.11 24.733,6.11 24.821,6.022 24.821,5.118 J3.3 24.8,3.78 25.296,3.284 27.296,3.284 v1(28,2.58)
  BOTTOM w0.15: v1(28,2.58) 30.6,2.58 J14.1
SD4_1: J6.3 J15.1 R10.1 U1.10 | length 19.8
  TOP w0.15: U1.10 24.179,9.355 R10.1 24.375,9.355 25.025,9.355 26.298,8.082 27.808,8.082 29.304,6.586 29.514,6.586 v1(29.6,6.5) ; J6.3@26.915,10.028 27.115,9.828 J6.3@27.134,9.809 ; J6.3 29.343,7.4 30,7.4 v1(30.9,6.5) 31.93,5.47 J15.1
  BOTTOM w0.15: v1(29.6,6.5) v1(30.9,6.5)
SD5_1: J9.3 J16.1 R12.1 U1.12 | length 15.7
  TOP w0.15: U1.12 23.068,11.88 23.228,11.88 R12.1 25.371,13.952 25.692,14.273 26.107,14.273 26.538,13.842 26.662,13.842 27.622,14.802 J9.3 27.645,14.825 v1(30.1,17.28) 30.1,20.562 30.98,21.442 31.802,21.442 J16.1
SD6_1: J10.3 J17.1 R14.1 U1.14 | length 18.4
  TOP w0.15: U1.14 22.798,13.917 22.798,17.788 23.098,18.088 23.623,18.088 24.1,18.565 24.1,19.051 23.8,19.351 23.8,21.52 24.06,21.78 27.7,21.78 28.751,22.831 30.651,22.831 J17.1
SD7_1: J5.3 J18.1 R16.1 U1.16 | length 18
  TOP w0.15: J18.1 13.54,22.18 15.6,22.18 16.2,21.58 J5.3 16.2,19.387 16.478,19.109 17.086,19.109 17.6,18.595 17.6,18.573 18.16,18.013 21.441,18.013 22.211,17.243 22.211,14.745 U1.16
SDA_1: J1.3 J4.3 J19.1 SDA.X U1.20 | length 49.4
  TOP w0.15: J19.1 9.378,12.988 10.786,12.988 11.641,13.843 11.641,15.502 13.428,17.289 15.226,17.289 15.34,17.174 15.986,17.174 16.245,17.433 17.49,17.433 17.741,17.182 19.308,17.182 19.61,16.88 v1(20.2,16.88) 20.2,16.462 19.46,15.722 19.46,14.781 U1.20 ; v1(33.6,16.98) 35.926,16.98 37.4,15.506 37.4,13.48 37.1,13.18 J4.3
  TOP w0.2: v1(3.9,12.5) 4.22,12.18 J1.3 J1.3@5.355,12.1
  BOTTOM w0.15: v1(20.2,16.88) 20.702,17.382 26.762,17.382 27.457,18.078 28.398,18.078 28.82,18.5 32.08,18.5 v1(33.6,16.98)
  BOTTOM w0.2: SDA.X 3.5,13.901 3.9,13.501 v1(3.9,12.5) 6.71,12.5 J19.1
pads on no net: Fiducial_1.1 Fiducial_2.1 Fiducial_3.1 NRST.X PA6.X PA7.X PC14.X PC15.X SWCLK.X SWDIO.X TP9.X TP10.X TP11.X TP12.X

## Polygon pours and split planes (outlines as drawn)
GND on TOP "NONET_L04_P-001" (solid, remove dead copper, pour order 2): 0,4.5 ccw(c4.5,4.5) 4.5,0 36.5,0 ccw(c36.5,4.5) 41,4.5 41,20.86 ccw(c36.5,20.86) 36.5,25.36 4.5,25.36 ccw(c4.5,20.86) 0,20.86
+3V3 on BOTTOM "NONET_L04_P-001" (solid, remove dead copper, pour order 3): 0,4.5 ccw(c4.5,4.5) 4.5,0 36.5,0 ccw(c36.5,4.5) 41,4.5 41,20.86 ccw(c36.5,20.86) 36.5,25.36 4.5,25.36 ccw(c4.5,20.86) 0,20.86

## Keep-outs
Keep-Out Layer:
  circle w0.05: c36.5,4.68 r2.75
  circle w0.05: c36.5,20.68 r2.75
  circle w0.05: c4.5,20.68 r2.75
  circle w0.05: c4.5,4.68 r2.75

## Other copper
BOTTOM:
  region: 597 vertices and 0 holes, not listed, extent 36.947,15.96 38.059,17.049

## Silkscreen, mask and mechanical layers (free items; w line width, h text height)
Route Tool Path:
  lines w2: -1,8.498 -1,16.86 ; 42,4.5 cw(c36.5,4.5) 36.5,-1 ; 42,8.498 42,16.86 ; -1,4.498 cw(c0,4.5) -1,4.5 ccw(c4.5,4.5) -1,4.498 ; -1,4.498 ccw(c4.5,4.5) 4.498,-1 ; -1,20.86 cw(c4.5,20.86) 4.5,26.36 ; -1,20.86 -1,20.86 ; 4.498,-1 ccw(c4.5,0) 4.5,-1 ; 4.498,-1 ccw(c4.5,4.5) 4.5,-1 ; 4.5,-1 36.5,-1 ; 4.5,26.36 4.5,26.36 ; 4.5,26.36 36.5,26.36 ; 36.5,-1 36.5,-1 ; 36.5,26.36 cw(c36.5,25.36) 36.502,26.36 ; 36.5,26.36 cw(c36.5,20.86) 36.502,26.36 ; 36.502,26.36 cw(c36.5,20.86) 42,20.863 ; 42,20.863 cw(c36.5,20.86) 42,20.86 ccw(c41,20.86) 42,20.863
Board:
  the board outline again, w0.05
